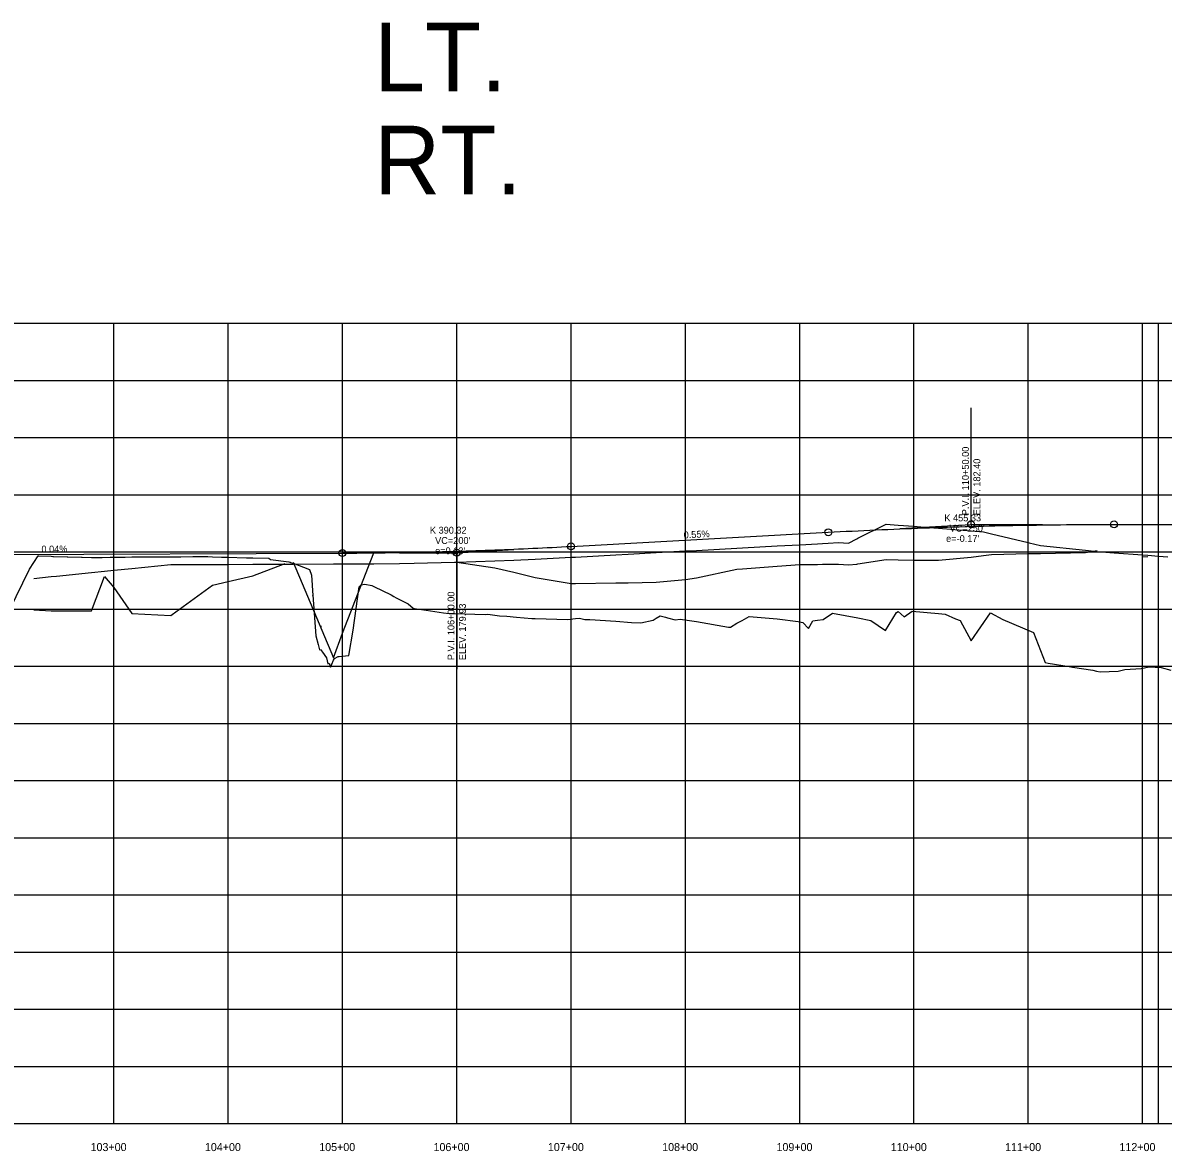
# Model space of a CAD drawing. Extents: x 915787 to 919910, y 133456 to 136717.
# Drawn here: x 917192 to 918190, y 135071 to 136058 of the extents above; entities that cross this region are included whole.
import ezdxf

# ---------------------------------------------------------------- set-up
doc = ezdxf.new("R2010")
doc.units = 0
for name, color, linetype in [('Default', 7, 'Continuous'), ('R_Axis', 7, 'Continuous'), ('R_Axis Annot', 7, 'Continuous'), ('R_Exist Surface', 7, 'Continuous'), ('R_Grid', 7, 'Continuous'), ('R_Proposed Const Limits', 7, 'Continuous'), ('R_Vert Alg', 7, 'Continuous'), ('R_Vert Alg Annot', 7, 'Continuous'), ('R_Water', 7, 'Continuous')]:
    doc.layers.add(name, color=color, linetype=linetype)

msp = doc.modelspace()

# ---------------------------------------------------------------- linework, layer by layer
at = {"layer": 'Default'}
msp.add_lwpolyline([(917201.67, 135571.77), (917217, 135573.31), (917221.67, 135573.78), (917252.28, 135576.86), (917263.67, 135578), (917271.67, 135578.81), (917287.57, 135580.4), (917321.67, 135583.83), (917322.85, 135583.84), (917358.13, 135583.97), (917371.67, 135584.02), (917393.41, 135584.1), (917421.67, 135584.2), (917428.69, 135584.23), (917463.97, 135584.35), (917471.67, 135584.38), (917499.25, 135584.58), (917521.67, 135584.89), (917534.53, 135585.12), (917569.81, 135585.98), (917571.67, 135586.03), (917605.09, 135587.15), (917621.67, 135587.81), (917640.38, 135588.65), (917671.67, 135590.24), (917675.66, 135590.46), (917710.94, 135592.4), (917721.67, 135592.99), (917746.22, 135594.33), (917771.67, 135595.73), (917781.5, 135596.27), (917816.78, 135598.21), (917821.67, 135598.48), (917852.06, 135600.14), (917871.67, 135601.22), (917887.34, 135602.08), (917891.67, 135602.32), (917896.67, 135602.59), (917905.69, 135603.08), (917914.42, 135602.69), (917921.67, 135606.43), (917922.62, 135606.92), (917947.42, 135619.18), (917957.9, 135618.42), (917971.67, 135617.4), (917980.67, 135616.7), (917993.19, 135615.71), (918021.67, 135613.31), (918032.42, 135612.36), (918039.42, 135610.74), (918071.67, 135603.12), (918072.42, 135602.94), (918082.42, 135600.53), (918121.67, 135596.41), (918131.79, 135595.3), (918131.8, 135595.3), (918146.67, 135594.19), (918171.67, 135592.3), (918176.17, 135591.96), (918185.57, 135591.24), (918193.74, 135590.62)], dxfattribs=at)
at = {"layer": 'R_Axis'}
msp.add_line((916971.67, 135094.96), (919871.67, 135094.96), dxfattribs=at)
at = {"layer": 'R_Exist Surface'}
msp.add_lwpolyline([(917180.4, 135543.95), (917197.96, 135579.87), (917205.56, 135591.37), (917206.05, 135591.37), (917217, 135591.06), (917218.22, 135591.02), (917218.82, 135591.02), (917230.89, 135590.7), (917231.43, 135590.7), (917243.56, 135590.37), (917244.03, 135590.37), (917252.28, 135590.15), (917256.23, 135590.04), (917256.51, 135590.04), (917261.5, 135590.16), (917268.55, 135590.25), (917268.9, 135590.25), (917280.61, 135590.4), (917281.55, 135590.4), (917287.57, 135590.47), (917292.54, 135590.5), (917294.2, 135590.48), (917304.29, 135590.53), (917306.85, 135590.51), (917312.69, 135590.61), (917322.85, 135590.65), (917330.3, 135590.64), (917340.82, 135590.79), (917353.65, 135590.81), (917353.82, 135590.8), (917358.13, 135590.69), (917365.88, 135590.44), (917371.21, 135590.45), (917387.68, 135589.78), (917388.49, 135589.78), (917392.05, 135589.67), (917393.41, 135589.67), (917407.18, 135589.58), (917408.67, 135588.23), (917424.86, 135586.2), (917425.57, 135585.97), (917425.86, 135585.94), (917426.25, 135585.75), (917428.69, 135584.96), (917442.87, 135579.65), (917444.56, 135574.64), (917445.67, 135556.79), (917445.84, 135556.98), (917448.38, 135521.58), (917450.49, 135513.99), (917451.48, 135509.38), (917452.38, 135509.71), (917454.26, 135507.29), (917457.6, 135502.35), (917458.84, 135497.12), (917459.97, 135497.61), (917461.34, 135494.19), (917462.31, 135496.85), (917463.97, 135500.11), (917464.85, 135501.83), (917467.93, 135503.43), (917467.94, 135503.43), (917468.89, 135503.37), (917477.31, 135504.46), (917480.97, 135526.48), (917486.25, 135564.48), (917487.97, 135566.24), (917491.22, 135566.78), (917497.44, 135565.46), (917499.25, 135564.65), (917514.39, 135557.4), (917516.69, 135555.9), (917518.56, 135554.77), (917529.2, 135549.47), (917533.69, 135545.66), (917534.53, 135545.54), (917544.93, 135543.88), (917560.05, 135541.66), (917565.05, 135541), (917569.81, 135540.95), (917596.68, 135540.33), (917598.97, 135540.4), (917605.09, 135539.64), (917609.01, 135539.13), (917615.63, 135538.8), (917623.98, 135537.97), (917637.44, 135536.79), (917640.38, 135536.72), (917668.98, 135535.75), (917675.66, 135536.66), (917679.11, 135537.09), (917683.69, 135535.75), (917688.19, 135535.7), (917710.94, 135534.24), (917724.67, 135533.23), (917732.85, 135533), (917743.54, 135535.27), (917746.22, 135536.93), (917749.67, 135538.98), (917754.15, 135537.87), (917756.09, 135537.25), (917762.65, 135535.61), (917767.23, 135536.11), (917781.5, 135533.92), (917809.28, 135529.1), (917810.02, 135529.19), (917810.39, 135529.21), (917811.03, 135529.25), (917816.78, 135532.48), (917821.33, 135534.96), (917827.45, 135538.3), (917852.06, 135536.25), (917870.27, 135534.19), (917874.55, 135533.33), (917879.4, 135527.94), (917883.23, 135534.6), (917887.34, 135535.19), (917892.21, 135535.73), (917900.36, 135541.35), (917922.62, 135537.3), (917933.97, 135534.88), (917946.75, 135526.3), (917956.39, 135542.01), (917957.89, 135542.93), (917957.9, 135542.92), (917963.19, 135538.19), (917970.17, 135543.14), (917993.19, 135541.05), (917999.01, 135540.41), (918007.85, 135536.32), (918012.08, 135534.94), (918021.82, 135517.14), (918038.47, 135541.68), (918049.31, 135535.73), (918076.14, 135524.51), (918086.37, 135498.24), (918089.09, 135497.65), (918107.41, 135494.8), (918110.33, 135494.16), (918128.18, 135491.37), (918131.28, 135490.69), (918134.46, 135489.98), (918150.22, 135490.74), (918156.04, 135492.05), (918170.49, 135492.95), (918177.32, 135494.46), (918187.93, 135493.78), (918196.44, 135491.57)], dxfattribs=at)
at = {"layer": 'R_Grid'}
for p, q in [((916971.67, 135794.96), (919871.67, 135794.96)), ((916971.67, 135794.96), (919871.67, 135794.96)), ((917271.67, 135094.96), (917271.67, 135794.96)), ((917371.67, 135094.96), (917371.67, 135794.96)), ((917471.67, 135094.96), (917471.67, 135794.96)), ((917571.67, 135094.96), (917571.67, 135794.96)), ((917671.67, 135094.96), (917671.67, 135794.96)), ((917771.67, 135094.96), (917771.67, 135794.96)), ((917871.67, 135094.96), (917871.67, 135794.96)), ((917971.67, 135094.96), (917971.67, 135794.96)), ((918071.67, 135094.96), (918071.67, 135794.96)), ((918171.67, 135094.96), (918171.67, 135794.96)), ((916971.67, 135744.96), (919871.67, 135744.96)), ((916971.67, 135694.96), (919871.67, 135694.96)), ((916971.67, 135644.96), (919871.67, 135644.96)), ((916971.67, 135594.96), (919871.67, 135594.96)), ((916971.67, 135544.96), (919871.67, 135544.96)), ((916971.67, 135494.96), (919871.67, 135494.96)), ((916971.67, 135444.96), (919871.67, 135444.96)), ((916971.67, 135394.96), (919871.67, 135394.96)), ((916971.67, 135344.96), (919871.67, 135344.96)), ((916971.67, 135294.96), (919871.67, 135294.96)), ((916971.67, 135244.96), (919871.67, 135244.96)), ((916971.67, 135194.96), (919871.67, 135194.96)), ((916971.67, 135144.96), (919871.67, 135144.96))]:
    msp.add_line(p, q, dxfattribs=at)
at = {"layer": 'R_Proposed Const Limits'}
for points in [[(917428.69, 135586.06), (917463.97, 135502.42), (917471.67, 135523.82), (917499.25, 135594.12)], [(917571.67, 135585.91), (917605.09, 135581.06), (917621.67, 135577.21), (917640.38, 135572.55), (917671.67, 135567.16), (917675.66, 135567.17), (917710.94, 135567.74), (917721.67, 135567.94), (917746.22, 135568.37), (917771.67, 135570.71), (917781.5, 135572.35), (917816.78, 135579.79), (917821.67, 135580.09), (917852.06, 135582.42), (917871.67, 135583.8), (917887.34, 135583.98), (917891.67, 135584.25), (917896.67, 135584.26), (917905.69, 135584.13), (917914.42, 135583.49), (917921.67, 135584.34), (917922.62, 135584.59), (917947.42, 135588.39), (917957.9, 135588.07), (917971.67, 135587.77), (917980.67, 135587.78), (917993.19, 135587.65), (918021.67, 135590.19), (918032.42, 135591.68), (918039.42, 135592.63), (918071.67, 135593.56), (918072.42, 135593.54), (918082.42, 135593.62), (918121.67, 135594.39), (918131.79, 135596.05)], [(918171.67, 135590.48), (918176.17, 135590.91)], [(917201.67, 135544.18), (917217, 135543.53), (917221.67, 135543.26), (917252.28, 135543.43), (917263.67, 135573.54), (917271.67, 135563.87), (917287.57, 135541.1), (917321.67, 135539.2), (917322.85, 135540.18), (917358.13, 135565.74), (917371.67, 135569.03), (917393.41, 135573.98), (917421.67, 135584.92)]]:
    msp.add_lwpolyline(points, dxfattribs=at)
at = {"layer": 'R_Vert Alg'}
for p, q in [((918021.67, 135618.96), (918021.67, 135720.96)), ((917671.67, 135599.74), (917896.67, 135612.09)), ((917959.17, 135615.53), (918021.67, 135618.96)), ((918021.67, 135618.96), (918084.17, 135618.96)), ((918146.67, 135618.96), (918631.67, 135618.96)), ((916972.71, 135592.05), (917471.67, 135593.88)), ((917521.67, 135594.07), (917571.67, 135594.25)), ((917571.67, 135594.25), (917621.67, 135596.99)), ((917571.67, 135594.25), (917571.67, 135492.25))]:
    msp.add_line(p, q, dxfattribs=at)
for points in [[(917896.67, 135612.09), (917901.88, 135612.38), (917907.09, 135612.65), (917912.3, 135612.92), (917917.51, 135613.19), (917922.72, 135613.45), (917927.92, 135613.7), (917933.13, 135613.95), (917938.34, 135614.19), (917943.55, 135614.43), (917948.76, 135614.66), (917953.97, 135614.88), (917959.17, 135615.1), (917964.38, 135615.31), (917969.59, 135615.51), (917974.8, 135615.71), (917980.01, 135615.91), (917985.22, 135616.09), (917990.42, 135616.28), (917995.63, 135616.45), (918000.84, 135616.62), (918006.05, 135616.79), (918011.26, 135616.94), (918016.47, 135617.09), (918026.88, 135617.38), (918032.09, 135617.51), (918037.3, 135617.64), (918042.51, 135617.77), (918047.72, 135617.88), (918052.92, 135617.99), (918058.13, 135618.1), (918063.34, 135618.19), (918068.55, 135618.29), (918073.76, 135618.37), (918078.97, 135618.45), (918084.17, 135618.53), (918089.38, 135618.6), (918094.59, 135618.66), (918099.8, 135618.72), (918105.01, 135618.77), (918110.22, 135618.81), (918115.42, 135618.85), (918120.63, 135618.88), (918125.84, 135618.91), (918131.05, 135618.93), (918136.26, 135618.94), (918141.47, 135618.95), (918146.67, 135618.96)], [(917471.67, 135593.88), (917475.84, 135593.9), (917480.01, 135593.92), (917484.17, 135593.95), (917488.34, 135593.98), (917492.51, 135594.01), (917496.67, 135594.05), (917500.84, 135594.1), (917505.01, 135594.15), (917509.17, 135594.2), (917513.34, 135594.26), (917517.51, 135594.32), (917521.67, 135594.39), (917525.84, 135594.46), (917530.01, 135594.53), (917534.17, 135594.61), (917538.34, 135594.7), (917542.51, 135594.79), (917546.67, 135594.88), (917550.84, 135594.98), (917555.01, 135595.08), (917559.17, 135595.18), (917563.34, 135595.3), (917567.51, 135595.41), (917575.84, 135595.65), (917580.01, 135595.78), (917584.17, 135595.92), (917588.34, 135596.05), (917592.51, 135596.2), (917596.67, 135596.34), (917600.84, 135596.49), (917605.01, 135596.65), (917609.17, 135596.81), (917613.34, 135596.97), (917617.51, 135597.14), (917621.67, 135597.31), (917625.84, 135597.49), (917630.01, 135597.67), (917634.17, 135597.86), (917638.34, 135598.05), (917642.51, 135598.25), (917646.67, 135598.45), (917650.84, 135598.65), (917655.01, 135598.86), (917659.17, 135599.07), (917663.34, 135599.29), (917667.51, 135599.51), (917671.67, 135599.74)]]:
    msp.add_lwpolyline(points, dxfattribs=at)
for centre in [(918021.67, 135618.96), (918146.67, 135618.96), (917896.67, 135612.09), (917671.67, 135599.74), (917471.67, 135593.88), (917571.67, 135594.25)]:
    msp.add_circle(centre, 3, dxfattribs=at)
at = {"layer": 'R_Water'}
for p, q in [((918185.57, 135094.96), (918185.57, 135794.96)), ((917487.67, 135564.6), (917487.67, 135565.14)), ((917674.67, 135567.17), (917674.67, 135567.22)), ((917675.67, 135567.17), (917675.67, 135567.22)), ((917251.67, 135543.43), (917251.67, 135543.37)), ((917452.67, 135530.21), (917452.67, 135529.2))]:
    msp.add_line(p, q, dxfattribs=at)

# ---------------------------------------------------------------- texts
at = {"layer": 'R_Axis Annot'}
for s, p in [('103+00', (917251.37, 135070.96)), ('104+00', (917351.37, 135070.96)), ('105+00', (917451.37, 135070.96)), ('106+00', (917551.37, 135070.96)), ('107+00', (917651.37, 135070.96)), ('108+00', (917751.37, 135070.96)), ('109+00', (917851.37, 135070.96)), ('110+00', (917951.37, 135070.96)), ('111+00', (918051.37, 135070.96)), ('112+00', (918151.37, 135070.96))]:
    msp.add_text(s, height=7, dxfattribs=at).set_placement(p)
at = {"layer": 'R_Vert Alg Annot'}
for s, rotation, p in [('P.V.I. 110+50.00', 90, (918019.67, 135626.96)), ('ELEV. 182.40', 90, (918029.67, 135626.96)), ('0.55%', 3.14266, (917770.31, 135606.66)), ('0.04%', 0.20996, (917208.39, 135594.42)), ('P.V.I. 106+00.00', 90, (917569.67, 135500.25)), ('ELEV. 179.93', 90, (917579.67, 135500.25))]:
    msp.add_text(s, height=6, rotation=rotation, dxfattribs=at).set_placement(p)
for s, p in [('K 455.33', (917998.23, 135621.64)), ('K 390.32', (917548.18, 135610.9)), ("VC=250'", (918002.77, 135612.64)), ("VC=200'", (917552.77, 135601.9)), ("e=-0.17'", (917999.77, 135603.64)), ("e=0.13'", (917552.77, 135592.9))]:
    msp.add_text(s, height=6, dxfattribs=at).set_placement(p)
at = {"layer": 'R_Water'}
for s, p in [('LT.', (917499.36, 135997.61)), ('RT.', (917499.36, 135907.61))]:
    msp.add_text(s, height=60, dxfattribs=at).set_placement(p)

doc.saveas('drawing.dxf')
